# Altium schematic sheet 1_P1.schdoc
size 307 x 218 mm; Symbol: Drawing-Symbol_A4; Device: Drawing-Symbol_A4; @Project Name: SDBlocker; @Page Count: 1; @Update Date: 2026-07-10; @Create Date: 2026-04-04; @Schematic Name: Schematic1; @Page No: 1; @Page Name: P1; Company: EasyEDA.com; Version: V1.0; Page Size: A4; @Create Time: 05:58:28; @Update Time: 13:57:32; Width: 1170; Height: 825; Region Start: 1; X Region Count: 6; Y Region Count: 4; Blade Width: 10; Title Block Position: 3; @Board Name: Board1
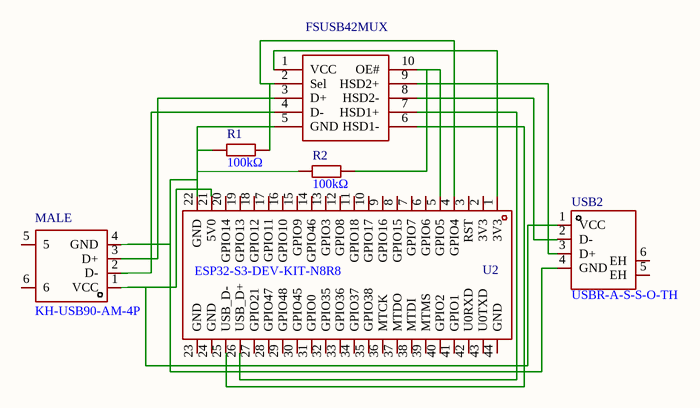
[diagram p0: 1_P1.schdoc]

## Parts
FSUSB42MUX  FSUSB42MUX  [MSOP-10_L3.0-W3.0-P0.50-LS5.0-BL]  (value not drawn)
MALE  KH-USB90-AM-4P  [USB-A-TH_917-181A202ED60201]
R1  100kΩ  [R1206]
R2  100kΩ  [R1206]
U2  ESP32-S3-DEV-KIT-N8R8  [COMM-TH_L63.3-W25.4-P2.54-LS22.86]
USB2  USBR-A-S-S-O-TH  [USB-TH_USBR-A-S-S-O-TH]

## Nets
NetFSUSB42MUX_1: FSUSB42MUX.1(VCC) U2.1(3V3)
NetFSUSB42MUX_2: FSUSB42MUX.2(Sel) R1.2 U2.4(GPIO4)
NetFSUSB42MUX_3: FSUSB42MUX.3(D+) MALE.3(D+)
NetFSUSB42MUX_4: FSUSB42MUX.4(D-) MALE.2(D-)
NetFSUSB42MUX_5: FSUSB42MUX.5(GND) MALE.4(GND) R1.1 R2.1 U2.22(GND) USB2.4(GND)
NetFSUSB42MUX_6: FSUSB42MUX.6(HSD1-) U2.25(USB_D-)
NetFSUSB42MUX_7: FSUSB42MUX.7(HSD1+) U2.26(USB_D+)
NetFSUSB42MUX_8: FSUSB42MUX.8(HSD2-) USB2.2(D-)
NetFSUSB42MUX_9: FSUSB42MUX.9(HSD2+) USB2.3(D+)
NetFSUSB42MUX_10: FSUSB42MUX.10(OE#) R2.2 U2.5(GPIO5)
NetMALE_1: MALE.1(VCC) U2.21(5V0) USB2.1(VCC)

Not connected (* = marked no-connect by the designer): MALE 5 6; U2 2(3V3) 3(RST) 6(GPIO6) 7(GPIO7) 8(GPIO15) 9(GPIO16) 10(GPIO17) 11(GPIO18) 12(GPIO8) 13(GPIO3) 14(GPIO46) 15(GPIO9) 16(GPIO10) 17(GPIO11) 18(GPIO12) 19(GPIO13) 20(GPIO14) 23(GND) 24(GND) 27(GPIO21) 28(GPIO47) 29(GPIO48) 30(GPIO45) 31(GPIO0) 32(GPIO35) 33(GPIO36) 34(GPIO37) 35(GPIO38) 36(MTCK) 37(MTDO) 38(MTDI) 39(MTMS) 40(GPIO2) 41(GPIO1) 42(U0RXD) 43(U0TXD) 44(GND); USB2 5(EH) 6(EH)

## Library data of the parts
FSUSB42MUX = FSUSB42MUX: Manufacturer: onsemi(安森美); Add into BOM: yes; Switch Circuit: 2:1; Number of Channels: 2; Supply Voltage: 3V~4.4V; Turn-on time: 13ns; On-State Resistance (Max): 6.5Ω; Turn-off time: 12ns; Ron: 3.9Ω; Con: 3.7pF; Bandwidth: 720MHz; Propagation Delay (tpd): 250ps
MALE = KH-USB90-AM-4P: Manufacturer: kinghelm(金航标); Add into BOM: yes; Connector Type: Type-A; Protocol Standard: USB 2.0; Gender: Male; Number of Contacts: 4P; Number of Ports: 1
R1 R2 = CR1206J100KP05Z: Manufacturer: EVER OHMS(天二科技); Symbol: 1206W4F1003T5E; Add into BOM: yes; Tolerance: ±5%; Power(Watts): 250mW; Voltage-Supply(Max): 200V; Temperature Coefficient: ±100ppm/℃
U2 = ESP32-S3-DEV-KIT-N8R8: Add into BOM: yes
USB2 = USBR-A-S-S-O-TH: Manufacturer: SAMTEC; Add into BOM: yes; Connector Type: Type-A; Protocol Standard: USB 2.0; Gender: Female; Number of Contacts: 4P; Number of Ports: 1; Voltage Rating: 30V; Detection color: Orange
